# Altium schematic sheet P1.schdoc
size 360 x 250 mm; Symbol: Drawing-Symbol_A4; Company: 嘉立创EDA; Version: V1.0; Page Size: A4; @Project Name: 220V转5V; @Update Date: 2026-02-28; @Create Date: 2026-02-28; Device: Drawing-Symbol_A4; @Board Name: Board1; @Page Name: P1; @Create Time: 19:56:47; @Page Count: 1; @Page No: 1; @Schematic Name: Schematic1; @Update Time: 19:56:47; @Assembly Variant: Basic; Border: 1; Title Block Position: 3; Size: A4; Width: 1417.3228346456692; Height: 984.251968503937; Region Start: 1; X Region Count: 6; Y Region Count: 4; Blade Width: 10; Title Block: 1
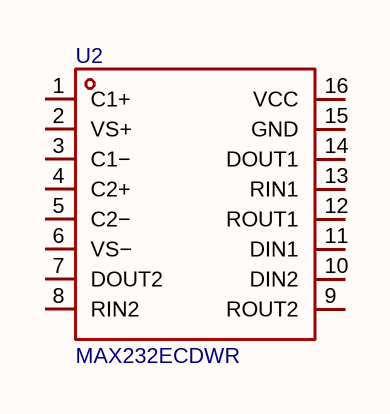
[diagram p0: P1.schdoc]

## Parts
U2  MAX232ECDWR  [SOIC-16_L10.3-W7.5-P1.27-LS10.3-BL]

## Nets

Not connected (* = marked no-connect by the designer): U2 1(C1+) 2(VS+) 3(C1−) 4(C2+) 5(C2−) 6(VS−) 7(DOUT2) 8(RIN2) 9(ROUT2) 10(DIN2) 11(DIN1) 12(ROUT1) 13(RIN1) 14(DOUT1) 15(GND) 16(VCC)

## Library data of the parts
U2 = MAX232ECDWR: 类型:收发器;数据速率:250Kbps;; Manufacturer: TI(德州仪器); AddInBom: yes; ModelId: 2da8125c657e49328ba6fa7b098653dd0819f05c4eef4c71ace90d822a990e87; ModelName: SOIC-16_L10.3-W7.5-H2.7-LS10.3-P1.27; ModelTransform: 405.511,409.68154,0,0,0,0,-0.0005,0,0; Number of Drivers: 2; Voltage - Supply: 4.5V~5.5V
